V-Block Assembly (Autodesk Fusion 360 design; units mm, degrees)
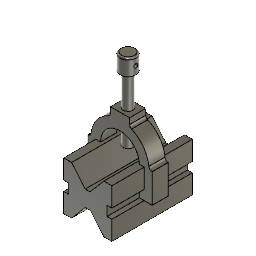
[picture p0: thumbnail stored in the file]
sketch "Sketch1" plane through (0, 0, 0) normal (0, 1, 0) x axis (1, 0, 0)
  line L1 (30, 30) -> (30, 6)
  line L2 (30, 6) -> (24, 6)
  line L3 (-24, -6) -> (-24, 6)
  line L4 (20, 30) -> (30, 30)
  line L5 (0, 0) -> (30.0388, 0)
  line L6 (30, -6) -> (30, -30)
  line L7 (30, -30) -> (20, -30)
  line L8 (20, -30) -> (3, -10)
  line L9 (-30, -6) -> (-24, -6)
  line L10 (-30, 30) -> (-20, 30)
  line L11 (24, -6) -> (30, -6)
  line L12 (-20, -30) -> (-30, -30)
  line L13 (3, 10) -> (20, 30)
  line L14 (-20, 30) -> (-3, 10)
  line L15 (0, -27.031) -> (0, 0)
  line L16 (-30, -30) -> (-30, -6)
  line L17 (3, -10) -> (-3, -10)
  line L18 (-30, 6) -> (-30, 30)
  line L19 (-3, -10) -> (-20, -30)
  line L20 (-24, 6) -> (-30, 6)
  line L21 (-3, 10) -> (3, 10)
  line L22 (24, 6) -> (24, -6)
  point P3 (0, 0)
  point P12 (0, 0)
  point P18 (3, -10)
  point P25 (-3, -10)
  point P4 (-20, -30)
  point P19 (20, -30)
  point P5 (-20, 30)
  point P13 (20, 30)
  point P8 (3, 10)
  point P10 (-3, 10)
  point P1 (0, 0)
  point P21 (30, -6)
  point P22 (24, -6)
  coincident P3 P12
  horizontal L5
  perpendicular L5 L15
  perpendicular L15 L17
  symmetric P18 P25 L15
  parallel L7 L17
  perpendicular L6 L7
  perpendicular L6 L11
  perpendicular L5 L22
  perpendicular L2 L22
  perpendicular L1 L2
  perpendicular L1 L4
  perpendicular L1 L21
  parallel L4 L10
  perpendicular L10 L18
  perpendicular L18 L20
  perpendicular L3 L10
  perpendicular L3 L9
  perpendicular L9 L16
  perpendicular L12 L16
  collinear L7 L12
  equal L7 L12
  symmetric P4 P19 L15
  equal L9 L11
  collinear L16 L18
  collinear L1 L6
  equal L3 L22
  symmetric L2 L5 L11
  collinear L9 L11
  equal L10 L12
  equal L4 L7
  collinear L4 L10
  equal L17 L21
  symmetric L5 L17 L21
  symmetric P5 P13 L15
  symmetric L4 L5 L7
  symmetric P8 P10 L15
  coincident P1 P12
  dimension "d1" distance P18 P25 = 6
  dimension "d2" distance P4 P19 = 40
  dimension "d3" distance L12 L17 = 20
  dimension "d4" distance P21 P22 = 6
  dimension "d5" distance L6 L16 = 60
  dimension "d6" distance L2 L11 = 12
  dimension "d7" distance L10 L12 = 60
extrude "Extrude1" new body sketch "Sketch1" profile of L1 L2 L3 L4 L6 L7 L8 L9 L10 L11 L12 L13 L14 L16 L17 L18 L19 L20 L21 L22 distance 50
sketch "Sketch1" plane through (0, 0, 0) normal (0, 1, 0) x axis (1, 0, 0)
  line L1 (-30, 30) -> (-30, 6)
  line L2 (-40, 6) -> (-30, 6)
  line L3 (-30, 6) -> (-24, 6)
  line L4 (-40, -30) -> (-40, 6)
  line L5 (-36, -30) -> (-40, -30)
  line L6 (40, 6) -> (30, 6)
  line L7 (40, -30) -> (40, 6)
  line L8 (36, -30) -> (40, -30)
  line L9 (-30, -30) -> (-20, -30)
  line L10 (20, -30) -> (30, -30)
  line L11 (12, -74) -> (12, -63.9411)
  line L12 (-12, -74) -> (12, -74)
  line L13 (-12, -63.9411) -> (-12, -74)
  line L14 (0, -83.1486) -> (0, 0)
  line L15 (-30, -30) -> (-24, -30)
  line L16 (-30, -6) -> (-30, -30)
  line L17 (-24, -6) -> (-30, -6)
  line L18 (-24, 6) -> (-24, -6)
  line L19 (-24, 6) -> (-30, 6)
  line L20 (30, -30) -> (24, -30)
  line L21 (30, -6) -> (30, -30)
  line L22 (24, -6) -> (30, -6)
  line L23 (24, 6) -> (24, -6)
  line L24 (30, 6) -> (24, 6)
  arc A1 centre (0, -30) radius 24 clockwise from (24, -30) to (-24, -30)
  arc A2 centre (0, -30) radius 36 clockwise from (-12, -63.9411) to (-36, -30)
  arc A3 centre (0, -30) radius 36 clockwise from (36, -30) to (12, -63.9411)
  point P2 (-30, 6)
  point P5 (-30, 6)
  point P10 (30, 6)
  point P11 (30, 6)
  point P17 (24, -30)
  point P16 (-24, -30)
  point P1 (0, 0)
  point P25 (0, 0)
  point P28 (12, -63.9411)
  point P18 (0, -30)
  point P22 (20, -30)
  point P20 (-30, -30)
  point P30 (-30, -30)
  point P32 (-30, -30)
  point P31 (-30, -6)
  point P33 (-30, -6)
  point P34 (-24, -6)
  point P35 (-24, -6)
  point P7 (-24, 6)
  point P36 (-24, 6)
  point P3 (-30, 6)
  point P37 (-30, 6)
  point P38 (-24, 6)
  point P21 (30, -30)
  point P39 (30, -30)
  point P41 (30, -30)
  point P40 (30, -6)
  point P42 (30, -6)
  point P43 (24, -6)
  point P44 (24, -6)
  point P45 (24, 6)
  point P46 (24, 6)
  point P47 (30, 6)
  point P23 (12, -74)
  point P24 (-12, -74)
  point P6 (-40, 6)
  point P8 (-40, -30)
  coincident P2 P5
  perpendicular L1 L2
  perpendicular L3 L4
  perpendicular L4 L5
  coincident P10 P11
  horizontal L6
  perpendicular L6 L7
  perpendicular L7 L8
  coincident P17 L10
  coincident P16 L9
  vertical L11
  horizontal L12
  vertical L13
  coincident P1 P25
  perpendicular L12 L14
  symmetric L11 L13 L14
  coincident P28 A2
  concentric A2 A3
  concentric A1 A2
  equal L4 L7
  equal L2 L6
  equal L5 L8
  horizontal P18 P22
  coincident P20 P30
  coincident P20 P32
  coincident P31 P33
  coincident P34 P35
  coincident P7 P36
  coincident P3 P37
  coincident P7 P38
  coincident P21 P39
  coincident P21 P41
  coincident P40 P42
  coincident P43 P44
  coincident P45 P46
  coincident P10 P47
  dimension "d10" distance P23 P24 = 24
  dimension "d11" distance L2 L12 = 80
  dimension "d13" distance P6 P8 = 36
  dimension "d14" radius A3 = 36
  dimension "d15" radius A1 = 24
  dimension "d16" distance L7 L23 = 16
extrude "Extrude1" new body sketch "Sketch1" profile of L2 L3 L4 L5 L6 L7 L8 A3 A1 L9 L10 L11 L12 L13 L15 L16 L17 L18 L19 L20 L21 L22 L23 L24 distance 10
sketch "Sketch2" plane through (0, 0, 74) normal (0, 0, 1) x axis (-1, 0, 0)
  line L1 (-12, -10) -> (-12, 10)
  line L2 (12, -10) -> (-12, -10)
  line L3 (12, 10) -> (12, -10)
  line L4 (-12, 10) -> (12, 10)
  circle C1 centre (0, 0) radius 6
  point P1 (0, 0)
  point P6 (0, 0)
  coincident P1 P6
  dimension "d19" diameter C1 = 12
extrude "Extrude2" cut sketch "Sketch2" profile of C1 to an object
fillet "Fillet1" radius 4
sketch "Sketch1" plane through (0, 0, 74) normal (0, 0, 1) x axis (-1, 0, 0)
  line L1 (-12, -10) -> (-12, 10)
  line L2 (12, -10) -> (-12, -10)
  line L3 (12, 10) -> (12, -10)
  line L4 (-12, 10) -> (12, 10)
  circle C1 centre (0, 0) radius 6
sketch "Sketch2" plane through (0, 0, 74) normal (0, 0, 1) x axis (-1, 0, 0)
  circle C1 centre (0, 0) radius 6
  point P1 (0, 0)
  point P2 (0, 0)
  coincident P1 P2
  dimension "d23" diameter C1 = 12
extrude "Extrude1" new body sketch "Sketch1" profile of C1 distance 80
sketch "Sketch3" plane through (0, 0, 114) normal (0, 0, 1) x axis (-1, 0, 0)
  circle C1 centre (0, 0) radius 6
  circle C2 centre (0, 0) radius 10
  point P1 (0, 0)
  point P3 (0, 0)
  coincident P1 P3
  dimension "d26" diameter C2 = 20
extrude "Extrude2" add sketch "Sketch3" along normal blind 20
sketch "Sketch4" plane through (0, 0, 0) normal (1, 0, 0) x axis (0, 1, 0)
  line L1 (-10, 134) -> (10, 134)
  circle C1 centre (0, 124) radius 2.5
  point P1 (0, 0)
  point P2 (0, 124)
  vertical P1 P2
  dimension "d29" diameter C1 = 5
  dimension "d30" distance P2 L1 = 10
extrude "Extrude3" cut sketch "Sketch4" profile of C1 no distance stored
fillet "Fillet1" radius 2
as_built_joint "As-built1" OffsetX 0 OffsetY 0 OffsetZ 0 AngleZ 0
as_built_joint "As-built2" OffsetX 0 OffsetY 0 OffsetZ 0 AngleZ 0
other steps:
create_component "CreateComponent1"
create_component "CreateComponent2"
create_component "CreateComponent3"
